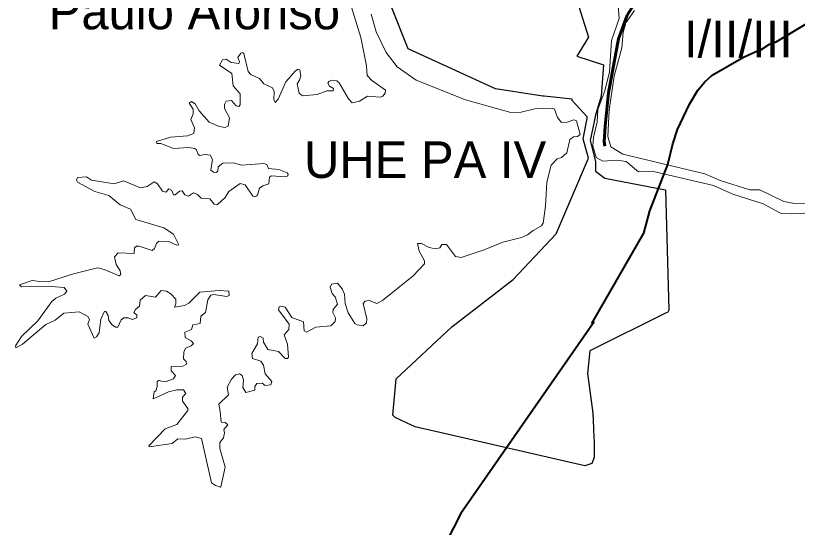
# Model space of a CAD drawing. Extents: x 553962 to 842807, y 8883888 to 9032388.
# Drawn here: x 579268 to 589939, y 8953669 to 8960655 of the extents above; entities that cross this region are included whole.
import ezdxf
from ezdxf.enums import TextEntityAlignment as Align

# ---------------------------------------------------------------- set-up
doc = ezdxf.new("R2010")
doc.units = 0
doc.header["$LTSCALE"] = 200
doc.linetypes.add('LONG_DASH_SHORT_DASH', pattern=[9.9, 6, -1.2, 1.5, -1.2])
for name, color, linetype, lineweight in [('12', 7, 'Continuous', 25), ('21', 7, 'Continuous', 25), ('25', 7, 'Continuous', 13), ('7', 7, 'LONG_DASH_SHORT_DASH', 60)]:
    doc.layers.add(name, color=color, linetype=linetype, lineweight=lineweight)
doc.layers.add('41', color=7, linetype='Continuous')
doc.layers.add('42', color=7, linetype='Continuous')

msp = doc.modelspace()

# ---------------------------------------------------------------- linework, layer by layer
at = {"layer": '12', "lineweight": 40}
for points in [[(587134, 8956453.8), (587843.6, 8957685.7), (587923.7, 8957988.5), (588169.9, 8958625.1), (588237, 8958904.7), (588304.1, 8959099.5), (588468, 8959448.9), (588578.9, 8959635.8), (588673.7, 8959750.1), (588777.5, 8959843.1), (589203.6, 8960089.7), (589393.4, 8960175.8), (589428.5, 8960178.5), (589560.1, 8960264.6), (589648.9, 8960297.2), (590059.4, 8960543.5), (591188.1, 8961101.4), (591408.7, 8961235.4), (591525.3, 8961280.9), (591868.7, 8961488.1), (592154.1, 8961587.2), (592311.1, 8961655)], [(587162.9, 8956477.1), (585344.2, 8953858.6), (584358.8, 8951929.6)]]:
    msp.add_lwpolyline(points, dxfattribs=at)
at = {"layer": '21'}
for points in [[(586058.4, 8957052.4), (586644.6, 8957678.4), (587088.5, 8958707.8), (587013.2, 8958975.6), (587068.3, 8959252.8), (587068.3, 8959273), (586866.5, 8959495), (586866.5, 8959515.2), (586483.1, 8959555.5), (586463, 8959555.5), (585817.3, 8959656.5), (584626.8, 8960201.4), (584162.8, 8961372.1)], [(586846.3, 8961129.9), (587088.5, 8960362.9), (586927, 8960100.5)], [(586927, 8960100.5), (587293.7, 8959984.2), (587261.8, 8959553.8), (587182.2, 8959298.7), (587110, 8958948.6), (587182.2, 8958662.7), (587182.2, 8958533.5), (587309.6, 8958437.9), (588138.3, 8958278.5)], [(588138.3, 8958278.5), (588184.9, 8956636.2), (588170.1, 8956606.6), (588147.9, 8956599.2), (587104, 8956080.8), (587074.4, 8955769.7), (587148.4, 8955229.1)], [(587148.4, 8955229.1), (587155.8, 8955021.8), (587155.8, 8954992.1), (587163.2, 8954829.2), (587163.2, 8954644.1), (587163.2, 8954621.8), (587133.6, 8954540.4), (587037.4, 8954510.8), (584720.1, 8955044), (584653.5, 8955073.6), (584631.3, 8955081), (584601.7, 8955095.8), (584446.2, 8955169.9), (584416.6, 8955199.5), (584461, 8955695.7), (585223.6, 8956406.6), (586058.4, 8957052.4)]]:
    msp.add_lwpolyline(points, dxfattribs=at)
at = {"layer": '25'}
for points in [[(582299.4, 8960082.5), (582339.6, 8960143.8), (582362.8, 8960152.2), (582381.9, 8960139.6), (582443.6, 8959893.3), (582477.6, 8959853), (582596.3, 8959797.7), (582656.1, 8959725.5), (582771.8, 8959670.2), (582795.6, 8959619.4), (582792, 8959510.9), (582809, 8959470.7), (582851.4, 8959515.1), (582957.8, 8959753.2), (583089.5, 8959901.9), (583125.3, 8959922.9), (583148.8, 8959914.2), (583159.4, 8959833.8), (583144.6, 8959774.5), (583108.6, 8959723.3), (583108.6, 8959723.3), (583138.3, 8959595.9), (583184.5, 8959559.9), (583382, 8959578.8), (583514.4, 8959627.7), (583603.4, 8959628), (583607.5, 8959661.8), (583550.2, 8959691.6), (583531.3, 8959731.8), (583541.6, 8959757), (583580.3, 8959774.3), (583651.7, 8959765.9), (583684, 8959740.2), (583809.5, 8959521.5), (583862.6, 8959466.3), (583962.4, 8959487.6), (584070.6, 8959557.6), (584244.7, 8959542.8), (584281, 8959557.7), (584312.8, 8959595.8), (584315, 8959638.2), (584126, 8959774.3), (584064.3, 8959836.4), (584055.9, 8959969.5), (583979.3, 8960356.6), (583690.5, 8961308.2)], [(582299.4, 8960082.5), (582339.6, 8960143.8), (582362.8, 8960152.2), (582381.9, 8960139.6), (582443.6, 8959893.3), (582477.6, 8959853), (582596.3, 8959797.7), (582656.1, 8959725.5), (582771.8, 8959670.2), (582795.6, 8959619.4), (582792, 8959510.9), (582809, 8959470.7), (582851.4, 8959515.1), (582957.8, 8959753.2), (583089.5, 8959901.9), (583125.3, 8959922.9), (583148.8, 8959914.2), (583159.4, 8959833.8), (583144.6, 8959774.5), (583108.6, 8959723.3), (583108.6, 8959723.3), (583138.3, 8959595.9), (583184.5, 8959559.9), (583382, 8959578.8), (583514.4, 8959627.7), (583603.4, 8959628), (583607.5, 8959661.8), (583550.2, 8959691.6), (583531.3, 8959731.8), (583541.6, 8959757), (583580.3, 8959774.3), (583651.7, 8959765.9), (583684, 8959740.2), (583809.5, 8959521.5), (583862.6, 8959466.3), (583962.4, 8959487.6), (584070.6, 8959557.6), (584244.7, 8959542.8), (584281, 8959557.7), (584312.8, 8959595.8), (584315, 8959638.2), (584126, 8959774.3), (584064.3, 8959836.4), (584055.9, 8959969.5), (583979.3, 8960356.6), (583690.5, 8961308.2)], [(587493.3, 8960783.2), (587506.9, 8960616.2), (587403.7, 8960314.5), (587373.8, 8959887.7), (587311.1, 8959628.3), (587213.9, 8959375.4), (587204.9, 8959204), (587155.6, 8958993.5), (587145.5, 8958878.4), (587193.6, 8958719.2), (587281.8, 8958666.6), (587474.7, 8958681.2), (587603.9, 8958663), (587767.8, 8958525.1), (587976.7, 8958527.1), (588793.4, 8958337.9), (589059.2, 8958220.1), (589471.1, 8958087), (589708, 8957957.9), (589856.5, 8957947.6), (590127.1, 8957964.8)], [(587368.2, 8959365.5), (587437, 8959830.7), (587541.6, 8960215), (587558.8, 8960425), (587596.7, 8960558.6), (587717.4, 8960723.2)], [(584121.2, 8960674.7), (584187.7, 8960432.6), (584325.6, 8960152.6), (584476.5, 8959954.9), (584733.5, 8959776.4), (585408.8, 8959506.7), (586028.5, 8959334.8), (586169.5, 8959338.8), (586356.5, 8959383.4), (586592.2, 8959394), (586621.9, 8959377), (586666.5, 8959264.6), (586719.8, 8959198.7), (586794.3, 8959202.9), (586887.5, 8959234.6), (586924.3, 8959221.3), (586974.5, 8959033.2), (586938.3, 8959007.4), (586883.3, 8959001), (586832.3, 8958962.8), (586791.8, 8958780.2), (586717.8, 8958720.8), (586660.1, 8958701.3), (586577.3, 8958614.2), (586518, 8958381), (586500.9, 8958053.6), (586466.9, 8957824.2), (586445.4, 8957783.8), (586330.8, 8957724.2), (586254.3, 8957662.7), (586173.8, 8957626.7)], [(584121.2, 8960674.7), (584187.7, 8960432.6), (584325.6, 8960152.6), (584476.5, 8959954.9), (584733.5, 8959776.4), (585408.8, 8959506.7), (586028.5, 8959334.8), (586169.5, 8959338.8), (586356.5, 8959383.4), (586592.2, 8959394), (586621.9, 8959377), (586666.5, 8959264.6), (586719.8, 8959198.7), (586794.3, 8959202.9), (586887.5, 8959234.6), (586924.3, 8959221.3), (586974.5, 8959033.2), (586938.3, 8959007.4), (586883.3, 8959001), (586832.3, 8958962.8), (586791.8, 8958780.2), (586717.8, 8958720.8), (586660.1, 8958701.3), (586577.3, 8958614.2), (586518, 8958381), (586500.9, 8958053.6), (586466.9, 8957824.2), (586445.4, 8957783.8), (586330.8, 8957724.2), (586254.3, 8957662.7), (586173.8, 8957626.7)], [(580099.6, 8958407.9), (580098.5, 8958410.3), (580113.2, 8958444.3), (580235.9, 8958453.9), (580303, 8958410.4), (580612.5, 8958359.6), (580740.2, 8958401.9), (580973.9, 8958304.4), (581064.7, 8958323.4), (581156.5, 8958384.9), (581203.2, 8958359.3), (581270.9, 8958257.8), (581319.8, 8958245), (581360.2, 8958291.4), (581400.5, 8958268.1), (581420.4, 8958210.8), (581447.3, 8958208.8), (581504.7, 8958259.6), (581539.6, 8958263.8), (581539.6, 8958263.8), (581578.9, 8958209), (581627.9, 8958191.9), (581696, 8958236.1), (581748.9, 8958212.8), (581799.4, 8958164.3), (581920, 8958154), (581978.5, 8958081.4), (582019.4, 8958072.8), (582127.2, 8958170.8), (582178.1, 8958253.3), (582332.9, 8958361.5), (582401, 8958344.6), (582505.1, 8958189.8), (582543.4, 8958185.4), (582568.8, 8958204.3), (582596.6, 8958300), (582641.2, 8958331.9), (582721.7, 8958357.6), (582732.5, 8958448.5), (582755.7, 8958467.7), (582953.2, 8958455.2), (582983.1, 8958470.1), (582989.4, 8958491.2), (582974.4, 8958510.4), (582859.9, 8958554.9), (582719.7, 8958570.1), (582696.2, 8958625.2), (582656.2, 8958635.6), (582353.6, 8958614.5), (582235.7, 8958646.3), (582095.5, 8958639.9), (582031.7, 8958591.2), (582027, 8958531.6), (582005.7, 8958514.7), (581967.3, 8958516.9), (581933.7, 8958544.9), (581955, 8958692.5), (581922.9, 8958748.3), (581848.8, 8958761), (581780.6, 8958746.3), (581757.5, 8958761.1), (581738.2, 8958822.6), (581712.6, 8958841.7), (581627.9, 8958854.5), (581424.2, 8958839.7), (581251.8, 8958907.5), (581194.6, 8958907.9), (581190.6, 8958937.3), (581381.2, 8958994.6), (581615.1, 8959015.9), (581699.9, 8959047.7), (581708.6, 8959122.1), (581659.8, 8959239), (581692.1, 8959315.5), (581691.6, 8959378.9), (581634.5, 8959460), (581670.4, 8959485.2), (581717.2, 8959451.2), (581774.6, 8959353.5), (581908.3, 8959202.9), (582046.5, 8959141.3), (582129.4, 8959128.6), (582167.3, 8959147.5), (582188.6, 8959260.2), (582118.7, 8959385.4), (582116.5, 8959440.5), (582142.1, 8959487.4), (582214.1, 8959495.9), (582278, 8959423.9), (582316.1, 8959415.5), (582331, 8959439.1), (582330.8, 8959589.7), (582237.6, 8959695.7), (582220.4, 8959865.6), (582050.7, 8959980.4), (582091.2, 8960052.6), (582141.7, 8960063.2), (582208.1, 8960016.5), (582315.9, 8960001.7), (582322.5, 8960029), (582299.4, 8960082.5)], [(580099.6, 8958407.9), (580098.5, 8958410.3), (580113.2, 8958444.3), (580235.9, 8958453.9), (580303, 8958410.4), (580612.5, 8958359.6), (580740.2, 8958401.9), (580973.9, 8958304.4), (581064.7, 8958323.4), (581156.5, 8958384.9), (581203.2, 8958359.3), (581270.9, 8958257.8), (581319.8, 8958245), (581360.2, 8958291.4), (581400.5, 8958268.1), (581420.4, 8958210.8), (581447.3, 8958208.8), (581504.7, 8958259.6), (581539.6, 8958263.8), (581539.6, 8958263.8), (581578.9, 8958209), (581627.9, 8958191.9), (581696, 8958236.1), (581748.9, 8958212.8), (581799.4, 8958164.3), (581920, 8958154), (581978.5, 8958081.4), (582019.4, 8958072.8), (582127.2, 8958170.8), (582178.1, 8958253.3), (582332.9, 8958361.5), (582401, 8958344.6), (582505.1, 8958189.8), (582543.4, 8958185.4), (582568.8, 8958204.3), (582596.6, 8958300), (582641.2, 8958331.9), (582721.7, 8958357.6), (582732.5, 8958448.5), (582755.7, 8958467.7), (582953.2, 8958455.2), (582983.1, 8958470.1), (582989.4, 8958491.2), (582974.4, 8958510.4), (582859.9, 8958554.9), (582719.7, 8958570.1), (582696.2, 8958625.2), (582656.2, 8958635.6), (582353.6, 8958614.5), (582235.7, 8958646.3), (582095.5, 8958639.9), (582031.7, 8958591.2), (582027, 8958531.6), (582005.7, 8958514.7), (581967.3, 8958516.9), (581933.7, 8958544.9), (581955, 8958692.5), (581922.9, 8958748.3), (581848.8, 8958761), (581780.6, 8958746.3), (581757.5, 8958761.1), (581738.2, 8958822.6), (581712.6, 8958841.7), (581627.9, 8958854.5), (581424.2, 8958839.7), (581251.8, 8958907.5), (581194.6, 8958907.9), (581190.6, 8958937.3), (581381.2, 8958994.6), (581615.1, 8959015.9), (581699.9, 8959047.7), (581708.6, 8959122.1), (581659.8, 8959239), (581692.1, 8959315.5), (581691.6, 8959378.9), (581634.5, 8959460), (581670.4, 8959485.2), (581717.2, 8959451.2), (581774.6, 8959353.5), (581908.3, 8959202.9), (582046.5, 8959141.3), (582129.4, 8959128.6), (582167.3, 8959147.5), (582188.6, 8959260.2), (582118.7, 8959385.4), (582116.5, 8959440.5), (582142.1, 8959487.4), (582214.1, 8959495.9), (582278, 8959423.9), (582316.1, 8959415.5), (582331, 8959439.1), (582330.8, 8959589.7), (582237.6, 8959695.7), (582220.4, 8959865.6), (582050.7, 8959980.4), (582091.2, 8960052.6), (582141.7, 8960063.2), (582208.1, 8960016.5), (582315.9, 8960001.7), (582322.5, 8960029), (582299.4, 8960082.5)], [(590089.5, 8958093.2), (589901.7, 8958091.4), (589756.1, 8958120.1), (589428.5, 8958275.3), (589288.6, 8958277.6), (588883.2, 8958402.7), (588677.6, 8958496.7), (587555.9, 8958762.2), (587392.7, 8958862), (587351, 8959003.1), (587368.2, 8959365.5)], [(579330.4, 8956970.9), (579320.1, 8956982.2), (579494.9, 8957040.3), (579635.1, 8957021.3), (579729, 8957025.6), (580056.8, 8957131.9), (580383.3, 8957210.3), (580477.4, 8957190.9), (580682.8, 8957104.2), (580701.6, 8957122.8), (580693.2, 8957169.7), (580640, 8957259.4), (580619.2, 8957363.6), (580667.8, 8957416.2), (580886.3, 8957410), (580890.9, 8957486.6), (580919.1, 8957507.7), (580955.2, 8957509.6), (581130.8, 8957450.5), (581162.8, 8957476.1), (581188.5, 8957544.2), (581224.5, 8957577.8), (581357.9, 8957571.4), (581466.2, 8957520.6), (581496, 8957526.9), (581421.8, 8957673.3), (581289.9, 8957760.6), (580910.1, 8957870.9), (580835.5, 8958013.2), (580692.5, 8958073.2), (580540.2, 8958198), (580349.1, 8958255.5), (580111.4, 8958382.8), (580099.6, 8958407.9)], [(579330.4, 8956970.9), (579320.1, 8956982.2), (579494.9, 8957040.3), (579635.1, 8957021.3), (579729, 8957025.6), (580056.8, 8957131.9), (580383.3, 8957210.3), (580477.4, 8957190.9), (580682.8, 8957104.2), (580701.6, 8957122.8), (580693.2, 8957169.7), (580640, 8957259.4), (580619.2, 8957363.6), (580667.8, 8957416.2), (580886.3, 8957410), (580890.9, 8957486.6), (580919.1, 8957507.7), (580955.2, 8957509.6), (581130.8, 8957450.5), (581162.8, 8957476.1), (581188.5, 8957544.2), (581224.5, 8957577.8), (581357.9, 8957571.4), (581466.2, 8957520.6), (581496, 8957526.9), (581421.8, 8957673.3), (581289.9, 8957760.6), (580910.1, 8957870.9), (580835.5, 8958013.2), (580692.5, 8958073.2), (580540.2, 8958198), (580349.1, 8958255.5), (580111.4, 8958382.8), (580099.6, 8958407.9)], [(586173.8, 8957626.7), (585918.1, 8957564.8), (585664, 8957458.9), (585351.4, 8957354.8), (585272.9, 8957365.6), (585149.7, 8957533.1), (585084, 8957533), (585058.5, 8957484.5), (584997.2, 8957473.7), (584911.7, 8957490.8), (584806, 8957543.7), (584753, 8957543.8), (584778.1, 8957437.9), (584848.5, 8957309.3), (584847.7, 8957267), (584696, 8957104.7), (584274.9, 8956764.4), (584197.5, 8956726), (584094.1, 8956768.4), (584038.7, 8956757.6), (584011.4, 8956727.3), (584062.2, 8956515.4), (584055.8, 8956462.4), (584011.2, 8956420.2), (583928.7, 8956432.8), (583896.6, 8956454.1), (583805.3, 8956596.4), (583767, 8956723.9), (583756.3, 8956851.3), (583724.4, 8956925.6), (583660.8, 8957002.1), (583580.2, 8956987.2), (583561.1, 8956946.9), (583586.5, 8956859.9), (583628.7, 8956817.4), (583660.7, 8956715.7), (583603.4, 8956642.9), (583599.3, 8956600.4), (583635.2, 8956528.2), (583628.9, 8956482), (583569.2, 8956422.2), (583365.5, 8956403), (583235.8, 8956333.2), (583204.2, 8956354.3), (583197.6, 8956473.1), (583036.3, 8956532.7), (582944.7, 8956675), (582889.9, 8956689.8), (582866.4, 8956681.3), (582857.8, 8956639.1), (583000.1, 8956445.4), (583000.1, 8956445.4), (582995.8, 8956371.3), (582932.2, 8956297.6), (582978.9, 8956171.6), (582991.4, 8955993), (582976.7, 8955976.2), (582947.1, 8955976.2), (582856.3, 8956071.3), (582711.3, 8956099.4), (582652.2, 8956196.2), (582645.2, 8956252.4), (582607.4, 8956273.4), (582579.8, 8956265), (582570.9, 8956175.6), (582492.5, 8956044.1), (582498.8, 8955974.4), (582613.2, 8955937.9), (582649.7, 8955884.6), (582675.3, 8955763.5), (582766.3, 8955661.9), (582751.6, 8955613.2), (582671.6, 8955604.4), (582632.4, 8955638.4), (582558.3, 8955632), (582532.9, 8955594), (582534.7, 8955540.7), (582411.8, 8955511), (582367.2, 8955576.8), (582379.8, 8955678.5), (582358.6, 8955744.6), (582321.7, 8955763.6), (582269.6, 8955750.9), (582214, 8955691.2), (582157.1, 8955581.8), (582171.5, 8955478.9), (582040.1, 8955351.6), (582061.2, 8955249.4), (582072.2, 8955107.3), (582129.2, 8955100.8), (582163, 8955071.2), (582108.2, 8955005.5), (582120.6, 8954960.7), (582103.7, 8954893.1), (582052.8, 8954828.8), (582057, 8954744.1), (582129.2, 8954489.4), (582066.7, 8954223.6)], [(586173.8, 8957626.7), (585918.1, 8957564.8), (585664, 8957458.9), (585351.4, 8957354.8), (585272.9, 8957365.6), (585149.7, 8957533.1), (585084, 8957533), (585058.5, 8957484.5), (584997.2, 8957473.7), (584911.7, 8957490.8), (584806, 8957543.7), (584753, 8957543.8), (584778.1, 8957437.9), (584848.5, 8957309.3), (584847.7, 8957267), (584696, 8957104.7), (584274.9, 8956764.4), (584197.5, 8956726), (584094.1, 8956768.4), (584038.7, 8956757.6), (584011.4, 8956727.3), (584062.2, 8956515.4), (584055.8, 8956462.4), (584011.2, 8956420.2), (583928.7, 8956432.8), (583896.6, 8956454.1), (583805.3, 8956596.4), (583767, 8956723.9), (583756.3, 8956851.3), (583724.4, 8956925.6), (583660.8, 8957002.1), (583580.2, 8956987.2), (583561.1, 8956946.9), (583586.5, 8956859.9), (583628.7, 8956817.4), (583660.7, 8956715.7), (583603.4, 8956642.9), (583599.3, 8956600.4), (583635.2, 8956528.2), (583628.9, 8956482), (583569.2, 8956422.2), (583365.5, 8956403), (583235.8, 8956333.2), (583204.2, 8956354.3), (583197.6, 8956473.1), (583036.3, 8956532.7), (582944.7, 8956675), (582889.9, 8956689.8), (582866.4, 8956681.3), (582857.8, 8956639.1), (583000.1, 8956445.4), (583000.1, 8956445.4), (582995.8, 8956371.3), (582932.2, 8956297.6), (582978.9, 8956171.6), (582991.4, 8955993), (582976.7, 8955976.2), (582947.1, 8955976.2), (582856.3, 8956071.3), (582711.3, 8956099.4), (582652.2, 8956196.2), (582645.2, 8956252.4), (582607.4, 8956273.4), (582579.8, 8956265), (582570.9, 8956175.6), (582492.5, 8956044.1), (582498.8, 8955974.4), (582613.2, 8955937.9), (582649.7, 8955884.6), (582675.3, 8955763.5), (582766.3, 8955661.9), (582751.6, 8955613.2), (582671.6, 8955604.4), (582632.4, 8955638.4), (582558.3, 8955632), (582532.9, 8955594), (582534.7, 8955540.7), (582411.8, 8955511), (582367.2, 8955576.8), (582379.8, 8955678.5), (582358.6, 8955744.6), (582321.7, 8955763.6), (582269.6, 8955750.9), (582214, 8955691.2), (582157.1, 8955581.8), (582171.5, 8955478.9), (582040.1, 8955351.6), (582061.2, 8955249.4), (582072.2, 8955107.3), (582129.2, 8955100.8), (582163, 8955071.2), (582108.2, 8955005.5), (582120.6, 8954960.7), (582103.7, 8954893.1), (582052.8, 8954828.8), (582057, 8954744.1), (582129.2, 8954489.4), (582066.7, 8954223.6)], [(579269.2, 8956128.5), (579267.5, 8956147.6), (579346.5, 8956275.5), (579569.6, 8956488.2), (579763, 8956751.6), (579818, 8956796.1), (579936.8, 8956853.3), (579964.5, 8956895.9), (579931, 8956942.9), (579750.3, 8956955.4), (579346.5, 8956953.4), (579330.4, 8956970.9)], [(579269.2, 8956128.5), (579267.5, 8956147.6), (579346.5, 8956275.5), (579569.6, 8956488.2), (579763, 8956751.6), (579818, 8956796.1), (579936.8, 8956853.3), (579964.5, 8956895.9), (579931, 8956942.9), (579750.3, 8956955.4), (579346.5, 8956953.4), (579330.4, 8956970.9)], [(581087.4, 8954777.9), (581086.2, 8954783.2), (581309.3, 8955015.9), (581466.6, 8955071.4), (581619.3, 8955264.8), (581619.2, 8955294.3), (581547.2, 8955390.1), (581547.2, 8955446.9), (581591.7, 8955496), (581559.6, 8955544.9), (581466.4, 8955547), (581352.5, 8955521.7), (581145.7, 8955426.2), (581160.6, 8955521.3), (581179.9, 8955534.8), (581200.8, 8955593.5), (581201, 8955657.4), (581215.8, 8955674.4), (581310.1, 8955657.7), (581421.9, 8955695.9), (581449.3, 8955742.7), (581390.1, 8955804.1), (581390.2, 8955865.7), (581551.4, 8955867.9), (581597.9, 8955895.3), (581593.8, 8955933.6), (581560, 8955969.8), (581562.1, 8956061.3), (581585.5, 8956114.1), (581661.8, 8956146.1), (581693.6, 8956177.9), (581665.8, 8956214.1), (581581.2, 8956260.8), (581578.8, 8956332.5), (581666, 8956369.2), (581685.3, 8956432.7), (581787.1, 8956452), (581795.2, 8956554.8), (581857.1, 8956604.5), (581891.2, 8956774.6), (581933.5, 8956840.4), (581969.4, 8956847.3), (582150.4, 8956819.5), (582182.3, 8956832.5), (582180, 8956896), (582043.8, 8956902.2), (581783.2, 8956880.5), (581783.2, 8956880.5), (581630, 8956728.1), (581572.6, 8956696.3), (581434.7, 8956673.2), (581455.8, 8956719.8), (581453.6, 8956783.3), (581388, 8956855.3), (581326.2, 8956893.7), (581251.9, 8956904.3), (581175.2, 8956811), (581041.6, 8956834.2), (580969.4, 8956772.7), (580958.6, 8956687.6), (580901.5, 8956645.2), (580882.6, 8956601.5), (580922.5, 8956566.6), (580922.4, 8956530.5), (580856.8, 8956505.1), (580801.5, 8956530.5), (580744, 8956530.4), (580708.6, 8956501.7), (580663.4, 8956403.2), (580631.7, 8956403.2), (580586.8, 8956433.1), (580540.2, 8956494.7), (580531.6, 8956562.6), (580499.8, 8956617.5), (580482.8, 8956619.5), (580431.9, 8956511.2), (580408.5, 8956324.5), (580372.3, 8956271.5), (580340.8, 8956252.5), (580251.5, 8956443.2), (580274.6, 8956509.1), (580253.4, 8956549.5), (580136.6, 8956613.3), (579924, 8956592), (579805, 8956498.6), (579677.6, 8956436.9), (579359.2, 8956171.6), (579269.9, 8956121.1), (579269.2, 8956128.5)], [(581087.4, 8954777.9), (581086.2, 8954783.2), (581309.3, 8955015.9), (581466.6, 8955071.4), (581619.3, 8955264.8), (581619.2, 8955294.3), (581547.2, 8955390.1), (581547.2, 8955446.9), (581591.7, 8955496), (581559.6, 8955544.9), (581466.4, 8955547), (581352.5, 8955521.7), (581145.7, 8955426.2), (581160.6, 8955521.3), (581179.9, 8955534.8), (581200.8, 8955593.5), (581201, 8955657.4), (581215.8, 8955674.4), (581310.1, 8955657.7), (581421.9, 8955695.9), (581449.3, 8955742.7), (581390.1, 8955804.1), (581390.2, 8955865.7), (581551.4, 8955867.9), (581597.9, 8955895.3), (581593.8, 8955933.6), (581560, 8955969.8), (581562.1, 8956061.3), (581585.5, 8956114.1), (581661.8, 8956146.1), (581693.6, 8956177.9), (581665.8, 8956214.1), (581581.2, 8956260.8), (581578.8, 8956332.5), (581666, 8956369.2), (581685.3, 8956432.7), (581787.1, 8956452), (581795.2, 8956554.8), (581857.1, 8956604.5), (581891.2, 8956774.6), (581933.5, 8956840.4), (581969.4, 8956847.3), (582150.4, 8956819.5), (582182.3, 8956832.5), (582180, 8956896), (582043.8, 8956902.2), (581783.2, 8956880.5), (581783.2, 8956880.5), (581630, 8956728.1), (581572.6, 8956696.3), (581434.7, 8956673.2), (581455.8, 8956719.8), (581453.6, 8956783.3), (581388, 8956855.3), (581326.2, 8956893.7), (581251.9, 8956904.3), (581175.2, 8956811), (581041.6, 8956834.2), (580969.4, 8956772.7), (580958.6, 8956687.6), (580901.5, 8956645.2), (580882.6, 8956601.5), (580922.5, 8956566.6), (580922.4, 8956530.5), (580856.8, 8956505.1), (580801.5, 8956530.5), (580744, 8956530.4), (580708.6, 8956501.7), (580663.4, 8956403.2), (580631.7, 8956403.2), (580586.8, 8956433.1), (580540.2, 8956494.7), (580531.6, 8956562.6), (580499.8, 8956617.5), (580482.8, 8956619.5), (580431.9, 8956511.2), (580408.5, 8956324.5), (580372.3, 8956271.5), (580340.8, 8956252.5), (580251.5, 8956443.2), (580274.6, 8956509.1), (580253.4, 8956549.5), (580136.6, 8956613.3), (579924, 8956592), (579805, 8956498.6), (579677.6, 8956436.9), (579359.2, 8956171.6), (579269.9, 8956121.1), (579269.2, 8956128.5)], [(582066.7, 8954223.6), (582065.2, 8954217.4), (581995.8, 8954238.9), (581939.2, 8954279.2), (581803.6, 8954880.3), (581719.8, 8954905.5), (581585.7, 8954873.7), (581483.7, 8954877.8), (581402.7, 8954812.1), (581089.5, 8954768.8), (581087.4, 8954777.9)], [(582066.7, 8954223.6), (582065.2, 8954217.4), (581995.8, 8954238.9), (581939.2, 8954279.2), (581803.6, 8954880.3), (581719.8, 8954905.5), (581585.7, 8954873.7), (581483.7, 8954877.8), (581402.7, 8954812.1), (581089.5, 8954768.8), (581087.4, 8954777.9)]]:
    msp.add_lwpolyline(points, dxfattribs=at)
at = {"layer": '7'}
msp.add_lwpolyline([(587540.9, 8964040.5), (587545.5, 8964019), (587739.9, 8963466), (587828.5, 8963155), (587886.8, 8963016.8), (588023, 8962809.1), (588321.3, 8962515.1), (588353.7, 8962454.8), (588379.7, 8962350), (588349.5, 8962039.7), (588356.1, 8961913.4), (588409.9, 8961732.7), (588515.9, 8961598.5), (588533, 8961520.2), (588511.4, 8961464.3), (588140, 8961216), (587908.2, 8961023.1), (587733.4, 8960846.2), (587616.5, 8960660), (587498.3, 8960337.4), (587362.2, 8959603), (587314, 8959147.2), (587303.2, 8958935.8), (587310.7, 8958873)], dxfattribs=at)

# ---------------------------------------------------------------- texts
at = {"layer": '41'}
msp.add_text('Paulo Afonso', height=500, dxfattribs=at).set_placement((581707.6, 8960468.8), align=Align.CENTER)
at = {"layer": '42'}
for s, p in [('I/II/III', (589134.4, 8960086.2)), ('UHE PA IV', (584857.3, 8958438.7))]:
    msp.add_text(s, height=500, dxfattribs=at).set_placement(p, align=Align.CENTER)

doc.saveas('drawing.dxf')
